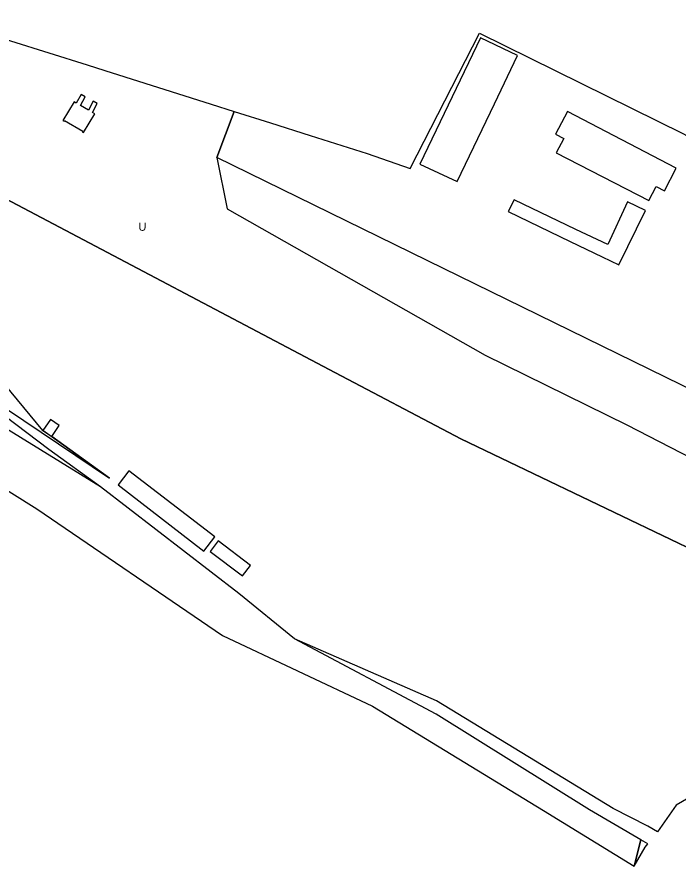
# Model space of a CAD drawing. Extents: x -749314 to -746497, y -1026537 to -1024935.
# Drawn here: x -747867.9 to -747665.9, y -1025657.5 to -1025397.9 of the extents above; entities that cross this region are included whole.
import ezdxf

# ---------------------------------------------------------------- set-up
doc = ezdxf.new("R2010")
doc.units = 0
for name, color, linetype in [('Default', 7, 'Continuous'), ('K_CD1', 7, 'Continuous'), ('K_DOSZDC1', 7, 'Continuous'), ('K_JVL', 7, 'Continuous'), ('K_SZDC1', 7, 'Continuous')]:
    doc.layers.add(name, color=color, linetype=linetype)

msp = doc.modelspace()

# ---------------------------------------------------------------- linework, layer by layer
at = {"layer": 'Default'}
msp.add_lwpolyline([(-747930.17, -1025466.36), (-747933.49, -1025464.6), (-747934.04, -1025464.31), (-747937.12, -1025470.28), (-747940.3, -1025471.24), (-747941.01, -1025471.45), (-747937.86, -1025472.92), (-747934.45, -1025474.52), (-747931.59, -1025475.86), (-747928.91, -1025478.73), (-747876.17, -1025514.34), (-747839.67, -1025538.87), (-747860, -1025524.32), (-747873.67, -1025507.89), (-747876.37, -1025512.29), (-747887.27, -1025505.61), (-747884.53, -1025501.19), (-747924.24, -1025469.51)], close=True, dxfattribs=at)
at = {"layer": 'K_CD1'}
for points in [[(-747806.89, -1025440.81), (-747803.65, -1025456.55), (-747724.81, -1025501.31), (-747681.55, -1025522.63), (-747651.76, -1025538.04), (-747633.28, -1025547.52), (-747623.29, -1025553.54), (-747594.59, -1025568.33), (-747507.39, -1025613.7), (-747488.27, -1025604.69), (-747507.44, -1025587.57), (-747572.94, -1025555.46), (-747737.58, -1025474.76)], [(-747861.81, -1025548.26), (-747805.1, -1025587.07), (-747759.25, -1025608.61), (-747707.06, -1025640.59), (-747679.31, -1025657.52), (-747677.31, -1025649.55), (-747692.95, -1025640.29), (-747739.79, -1025611.12), (-747783.16, -1025588.03), (-747800.16, -1025574.15), (-747842.35, -1025541.52), (-747879.17, -1025518.96), (-747936.59, -1025484.71), (-747947.31, -1025499.49), (-747917.02, -1025513.71)], [(-747839.67, -1025538.87), (-747860, -1025524.32), (-747857.3, -1025526.19)], [(-747675.19, -1025650.7), (-747677.31, -1025649.55), (-747679.31, -1025657.52), (-747675.92, -1025651.74)]]:
    msp.add_lwpolyline(points, close=True, dxfattribs=at)
at = {"layer": 'K_DOSZDC1'}
for points in [[(-747645.99, -1025568.28), (-747732.3, -1025526.84), (-747772.49, -1025505.64), (-747865.91, -1025456.37), (-747912.12, -1025432), (-747915.46, -1025430.24), (-747917.87, -1025428.97), (-747913.16, -1025420.04), (-747912.78, -1025419.32), (-747911.52, -1025420.04), (-747910.44, -1025420.66), (-747907.16, -1025422.53), (-747901.99, -1025412.07), (-747892.92, -1025397.87), (-747869.93, -1025405.14), (-747846.49, -1025412.54), (-747841.03, -1025414.26), (-747808.54, -1025424.53), (-747801.54, -1025426.74), (-747806.89, -1025440.81), (-747803.65, -1025456.55), (-747724.81, -1025501.31), (-747681.55, -1025522.63), (-747651.76, -1025538.04)], [(-747912.12, -1025432), (-747865.91, -1025456.37), (-747772.49, -1025505.64), (-747732.3, -1025526.84), (-747645.99, -1025568.28)], [(-747876.17, -1025514.34), (-747839.67, -1025538.87), (-747857.3, -1025526.19), (-747854.99, -1025522.82), (-747857.7, -1025520.96), (-747860, -1025524.32), (-747873.67, -1025507.89)], [(-747656.13, -1025632.86), (-747666.5, -1025638.88), (-747672.15, -1025647.1), (-747675.14, -1025645.35), (-747685.76, -1025639.91), (-747739.72, -1025607.03), (-747783.16, -1025588.03), (-747800.16, -1025574.15), (-747842.35, -1025541.52), (-747858.2, -1025530.1), (-747871.62, -1025519.95)]]:
    msp.add_lwpolyline(points, dxfattribs=at)
for points in [[(-747853.86, -1025429.57), (-747853.51, -1025429.77), (-747853.35, -1025429.49), (-747847.78, -1025432.74), (-747847.95, -1025433.03), (-747847.6, -1025433.23), (-747844.17, -1025427.47), (-747844.86, -1025427.07), (-747843.41, -1025424.35), (-747844.68, -1025423.64), (-747846.1, -1025426.34), (-747848.49, -1025424.94), (-747847.07, -1025422.3), (-747848.32, -1025421.6), (-747849.78, -1025424.18), (-747850.47, -1025423.78)], [(-747836.97, -1025540.96), (-747810.78, -1025561.24), (-747807.45, -1025556.83), (-747833.71, -1025536.64)], [(-747808.87, -1025561.29), (-747799.02, -1025568.79), (-747796.56, -1025565.6), (-747806.43, -1025558.09)]]:
    msp.add_lwpolyline(points, close=True, dxfattribs=at)
at = {"layer": 'K_JVL'}
for points in [[(-747806.89, -1025440.81), (-747801.54, -1025426.74), (-747790.47, -1025430.23), (-747778.3, -1025434.08), (-747760.89, -1025439.58), (-747747.8, -1025444.16), (-747726.55, -1025402.81), (-747672.3, -1025429.68), (-747664.28, -1025433.65), (-747604.27, -1025466.43), (-747591.06, -1025474.03), (-747578.07, -1025477.88), (-747578.44, -1025479.13), (-747574.29, -1025488.05), (-747567.97, -1025500.24), (-747560.09, -1025525.41), (-747546.55, -1025552.64), (-747507.44, -1025587.57), (-747572.94, -1025555.46), (-747737.58, -1025474.76)], [(-747722.05, -1025424.48), (-747714.94, -1025409.67), (-747726.33, -1025404.26), (-747744.84, -1025442.88), (-747733.45, -1025448.22)], [(-747722.05, -1025424.48), (-747714.94, -1025409.67), (-747726.33, -1025404.26), (-747744.84, -1025442.88), (-747733.45, -1025448.22)], [(-747670.08, -1025451.01), (-747666.49, -1025444.06), (-747699.73, -1025426.73), (-747703.36, -1025433.72), (-747700.83, -1025435.05), (-747703.12, -1025439.43), (-747674.89, -1025454.04), (-747672.62, -1025449.69)], [(-747670.08, -1025451.01), (-747666.49, -1025444.06), (-747699.73, -1025426.73), (-747703.36, -1025433.72), (-747700.83, -1025435.05), (-747703.12, -1025439.43), (-747674.89, -1025454.04), (-747672.62, -1025449.69)], [(-747697.16, -1025462.82), (-747716.03, -1025453.77), (-747717.79, -1025457.4), (-747698.91, -1025466.53), (-747689.15, -1025471.25), (-747684.06, -1025473.71), (-747675.89, -1025457.1), (-747681.32, -1025454.43), (-747687.41, -1025467.5)], [(-747697.16, -1025462.82), (-747716.03, -1025453.77), (-747717.79, -1025457.4), (-747698.91, -1025466.53), (-747689.15, -1025471.25), (-747684.06, -1025473.71), (-747675.89, -1025457.1), (-747681.32, -1025454.43), (-747687.41, -1025467.5)]]:
    msp.add_lwpolyline(points, close=True, dxfattribs=at)
at = {"layer": 'K_SZDC1'}
for points in [[(-747853.35, -1025429.49), (-747847.78, -1025432.74), (-747847.95, -1025433.03), (-747847.6, -1025433.23), (-747844.17, -1025427.47), (-747844.86, -1025427.07), (-747843.41, -1025424.35), (-747844.68, -1025423.64), (-747846.1, -1025426.34), (-747848.49, -1025424.94), (-747847.07, -1025422.3), (-747848.32, -1025421.6), (-747849.78, -1025424.18), (-747850.47, -1025423.78), (-747853.86, -1025429.57), (-747853.51, -1025429.77)], [(-747857.7, -1025520.96), (-747860, -1025524.32), (-747857.3, -1025526.19), (-747854.99, -1025522.82)], [(-747810.78, -1025561.24), (-747807.45, -1025556.83), (-747833.71, -1025536.64), (-747836.97, -1025540.96)], [(-747806.43, -1025558.09), (-747808.87, -1025561.29), (-747799.02, -1025568.79), (-747796.56, -1025565.6)]]:
    msp.add_lwpolyline(points, close=True, dxfattribs=at)

# ---------------------------------------------------------------- texts
msp.add_text('U', height=2.5).set_placement((-747830.79, -1025463.25))

doc.saveas('drawing.dxf')
